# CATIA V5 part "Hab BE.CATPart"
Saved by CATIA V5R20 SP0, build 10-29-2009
Part number: Hab BE
Bounding box of the stored display mesh (mm): x 0 to 10, y -419.306 to 221.491, z -437.333 to 3.383
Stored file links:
  D:\Dropbox\IAO_2012\IAO_2012_766_vlaroche\vlaroche\vlaroche\IAO\A rendre\Hab BE.CATPart
  D:\Catia\IAO\A rendre\Assemblage.CATProduct
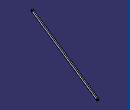
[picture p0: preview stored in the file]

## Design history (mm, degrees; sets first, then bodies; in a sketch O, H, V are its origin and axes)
Set1
  Point1: linked copy from another document
  Point2: linked copy from another document
Body1 (main body)
  Sketch1 on yz-plane, origin (0, 0, 0), H (0, 1, 0), V (0, 0, 1)
    construction line L1 (-409.3323, -6.5908) -> (211.517, -427.3593)
    point P1 (-409.3323, -6.5908)
    point P2 (211.517, -427.3593)
    line L2 (-403.7221, 1.6872) -> (217.1273, -419.0813)
    line L3 (205.9068, -435.6373) -> (-414.9426, -14.8688)
    arc A1 centre (211.517, -427.3593) radius 10 from (217.1273, -419.0813) to (205.9068, -435.6373) cw
    arc A2 centre (-409.3323, -6.5908) radius 10 from (-414.9426, -14.8688) to (-403.7221, 1.6872) cw
    reference projected point E1 (-409.3323, -6.5908) from Point1
    reference projected point E2 (211.517, -427.3593) from Point2
    circle A3 centre (-409.3323, -6.5908) radius 5
    circle A4 centre (211.517, -427.3593) radius 5
    point P7 (211.517, -427.3593)
    distance L1 L2 = 10
    radius A3 = 5
    radius A4 = 5
    tangency: A1 L2, A2 L2, A1 L3, A2 L3
    coincidence: P1 E1, P2 E2, P7 L1
  Pad1: profile Sketch1, direction (1, 0, 0), length 10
